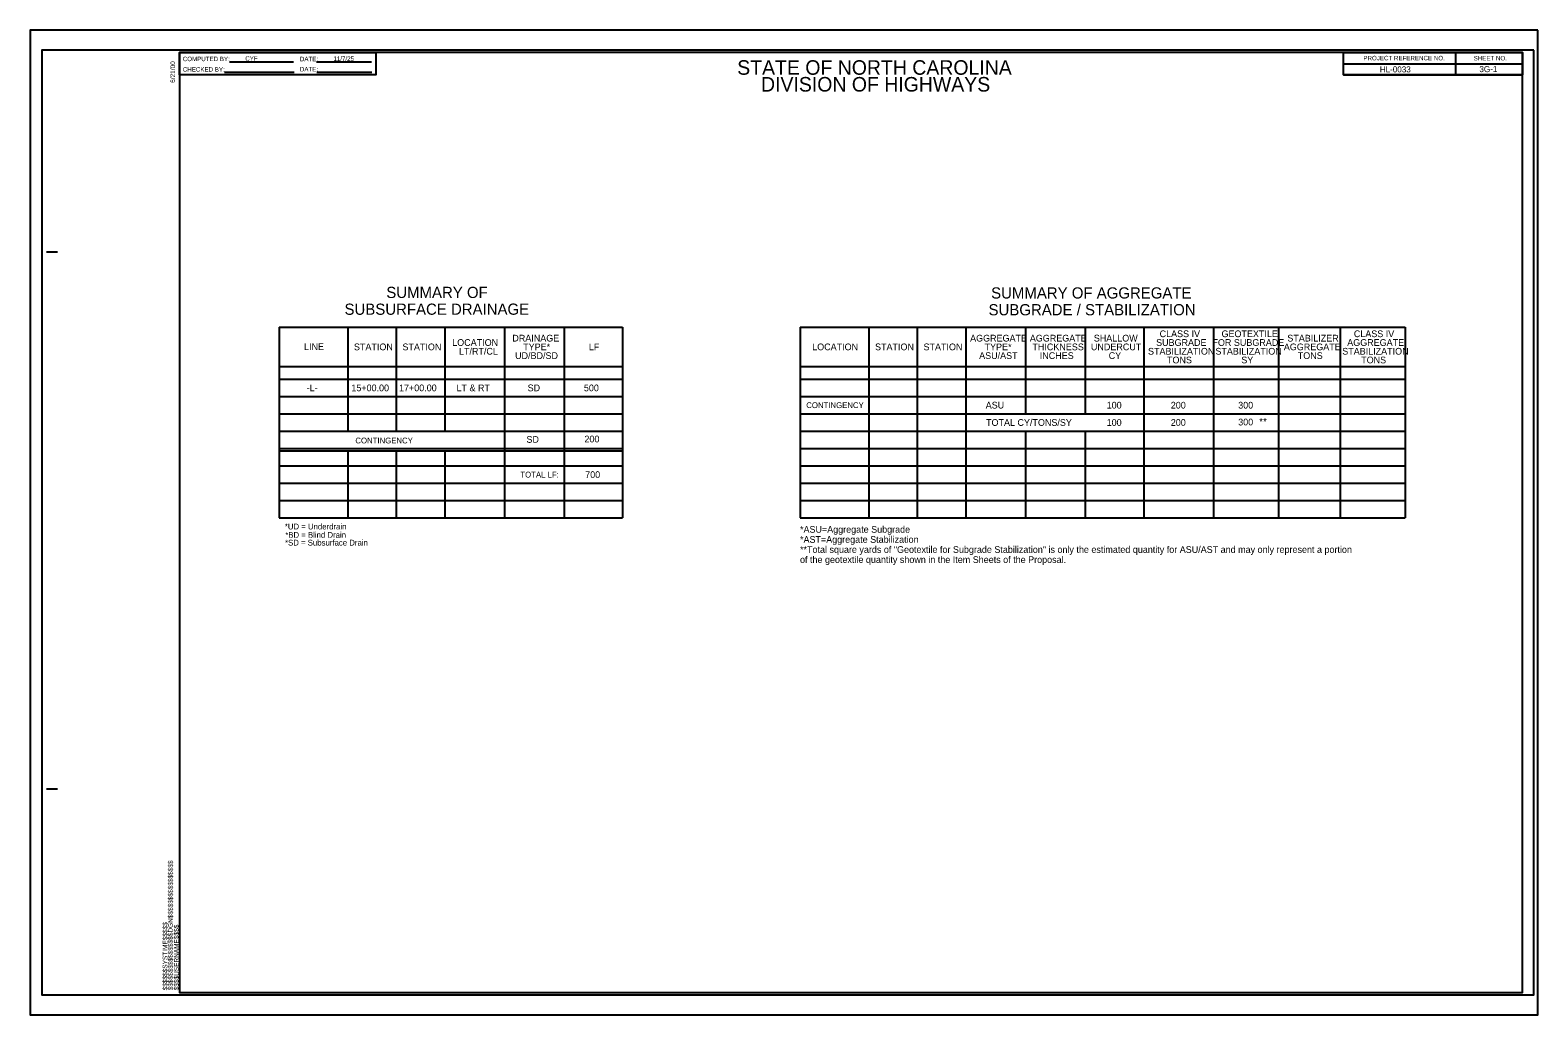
# Model space of a CAD drawing. Extents: x 971219 to 971893, y 692895 to 693335.
import ezdxf

# ---------------------------------------------------------------- set-up
doc = ezdxf.new("R2010")
doc.units = 0
for name, color, linetype in [('Old_Level_1', 7, 'Continuous'), ('Sheet Cutting Line CELL', 7, 'Continuous'), ('Sheet Data Field CELL', 7, 'Continuous'), ('Sheet Plot Border Inside CELL', 7, 'Continuous'), ('Sheet Plot Border Outside CELL', 7, 'Continuous'), ('Sheet Sticker Preliminary CELL', 7, 'Continuous'), ('Sheet Summary Earthwork CELL', 7, 'Continuous')]:
    doc.layers.add(name, color=color, linetype=linetype)

msp = doc.modelspace()

# ---------------------------------------------------------------- linework, layer by layer
at = {"layer": 'Sheet Cutting Line CELL'}
for p, q in [((971893.09, 693334.98), (971219.49, 693334.98)), ((971219.49, 693334.98), (971219.49, 692894.98)), ((971219.49, 692894.98), (971893.09, 692894.98))]:
    msp.add_line(p, q, dxfattribs=at)
at = {"layer": 'Sheet Plot Border Inside CELL'}
msp.add_lwpolyline([(971891.29, 693326), (971224.69, 693326), (971224.69, 692903.96), (971891.29, 692903.96)], close=True, dxfattribs=at)
at = {"layer": 'Sheet Plot Border Outside CELL'}
msp.add_lwpolyline([(971893.09, 693334.98), (971219.49, 693334.98), (971219.49, 692894.98), (971893.09, 692894.98)], close=True, dxfattribs=at)
at = {"layer": 'Sheet Sticker Preliminary CELL'}
for p, q in [((971856.29, 693324.96), (971856.29, 693314.96)), ((971308.55, 693320.82), (971337.17, 693320.82)), ((971347.49, 693320.76), (971372.05, 693320.76)), ((971806.27, 693319.96), (971886.29, 693319.96)), ((971306.37, 693316.14), (971337.45, 693316.14)), ((971347.55, 693316.16), (971372.11, 693316.16)), ((971806.27, 693314.96), (971886.29, 693314.96)), ((971226.73, 693235.98), (971231.73, 693235.98)), ((971459.63, 693202.24), (971459.63, 693202.24)), ((971692.44, 693202.24), (971692.44, 693202.24)), ((971226.73, 692995.98), (971231.73, 692995.98))]:
    msp.add_line(p, q, dxfattribs=at)
for points in [[(971886.29, 693324.98), (971286.29, 693324.98), (971286.29, 692904.98), (971886.29, 692904.98)], [(971286.29, 693324.98), (971373.89, 693324.98), (971373.89, 693314.98), (971286.29, 693314.98)], [(971806.27, 693324.98), (971886.29, 693324.98), (971886.29, 693314.96), (971806.27, 693314.96)]]:
    msp.add_lwpolyline(points, close=True, dxfattribs=at)
at = {"layer": 'Sheet Summary Earthwork CELL'}
for p, q in [((971330.79, 693202.2), (971330.79, 693117.13)), ((971330.79, 693202.2), (971484.19, 693202.2)), ((971361.39, 693202.2), (971361.39, 693155.8)), ((971383.04, 693202.2), (971383.04, 693155.8)), ((971404.7, 693202.2), (971404.7, 693155.8)), ((971431.43, 693202.2), (971431.43, 693163.53)), ((971458.03, 693202.2), (971458.03, 693163.53)), ((971484.19, 693202.2), (971484.19, 693117.13)), ((971563.59, 693202.2), (971563.59, 693117.13)), ((971563.59, 693202.2), (971833.86, 693202.2)), ((971594.19, 693202.2), (971594.19, 693117.13)), ((971615.85, 693202.2), (971615.85, 693117.13)), ((971637.51, 693202.2), (971637.51, 693117.13)), ((971664.23, 693202.2), (971664.23, 693163.53)), ((971690.84, 693202.2), (971690.84, 693163.53)), ((971716.99, 693202.2), (971716.99, 693117.13)), ((971748.17, 693202.2), (971748.17, 693117.13)), ((971748.17, 693202.2), (971748.17, 693117.13)), ((971777.19, 693202.2), (971777.19, 693117.13)), ((971777.19, 693202.2), (971777.19, 693117.13)), ((971804.84, 693202.2), (971804.84, 693117.13)), ((971804.84, 693202.2), (971804.84, 693117.13)), ((971833.86, 693202.2), (971833.86, 693117.13)), ((971833.86, 693202.2), (971833.86, 693117.13)), ((971330.79, 693184.7), (971484.19, 693184.7)), ((971563.59, 693184.7), (971833.86, 693184.7)), ((971330.79, 693179), (971484.19, 693179)), ((971563.59, 693179), (971833.86, 693179)), ((971330.79, 693171.27), (971484.19, 693171.27)), ((971563.59, 693171.27), (971833.86, 693171.27)), ((971330.79, 693163.53), (971484.19, 693163.53)), ((971431.43, 693163.53), (971431.43, 693117.13)), ((971458.03, 693163.53), (971458.03, 693117.13)), ((971563.59, 693163.53), (971833.86, 693163.53)), ((971330.79, 693155.8), (971484.19, 693155.8)), ((971563.59, 693155.8), (971833.86, 693155.8)), ((971664.23, 693155.8), (971664.23, 693117.13)), ((971690.84, 693155.8), (971690.84, 693117.13)), ((971330.79, 693148.06), (971484.19, 693148.06)), ((971563.59, 693148.06), (971833.86, 693148.06)), ((971330.76, 693147), (971484.15, 693147)), ((971361.39, 693147), (971361.39, 693117.13)), ((971383.04, 693147), (971383.04, 693117.13)), ((971404.7, 693147), (971404.7, 693117.13)), ((971330.79, 693140.33), (971484.19, 693140.33)), ((971563.59, 693140.33), (971833.86, 693140.33)), ((971330.79, 693132.6), (971484.19, 693132.6)), ((971563.59, 693132.6), (971833.86, 693132.6)), ((971330.79, 693124.86), (971484.19, 693124.86)), ((971563.59, 693124.86), (971833.86, 693124.86)), ((971330.79, 693117.13), (971484.19, 693117.13)), ((971563.59, 693117.13), (971833.86, 693117.13))]:
    msp.add_line(p, q, dxfattribs=at)

# ---------------------------------------------------------------- texts
at = {"layer": 'Old_Level_1'}
for s, height, p in [('-L-', 3, (971343.01, 693173.63)), ('15+00.00', 3, (971362.99, 693173.63)), ('17+00.00', 3, (971384.28, 693173.63)), ('LT & RT', 3, (971409.97, 693173.63)), ('SD', 3, (971441.75, 693173.63)), ('500', 3, (971466.88, 693173.63)), ('CONTINGENCY', 2.6, (971566.24, 693166.1)), ('ASU', 3, (971646.41, 693165.91)), ('100', 3, (971700.45, 693165.9)), ('200', 3, (971729.11, 693165.9)), ('300', 3, (971759.21, 693165.9)), ('300', 3, (971759.22, 693158.35)), ('TOTAL CY/TONS/SY', 3, (971646.56, 693158.17)), ('100', 3, (971700.45, 693158.17)), ('200', 3, (971729.11, 693158.17)), ('CONTINGENCY', 2.6, (971364.79, 693150.31)), ('SD', 3, (971441.23, 693150.6)), ('200', 3, (971467.12, 693150.79)), ('TOTAL LF:', 2.6, (971438.51, 693135.07)), ('700', 3, (971467.47, 693134.9)), ('*UD = Underdrain', 2.6, (971333.27, 693111.88)), ('*BD = Blind Drain', 2.6, (971333.47, 693108.13)), ('*ASU=Aggregate Subgrade', 3, (971563.45, 693110.4)), ('*AST=Aggregate Stabilization', 3, (971563.45, 693105.9)), ('*SD = Subsurface Drain', 2.6, (971333.37, 693104.67)), ('**Total square yards of "Geotextile for Subgrade Stabilization" is only the estimated quantity for ASU/AST and may only represent a portion', 3, (971563.45, 693101.4)), ('of the geotextile quantity shown in the Item Sheets of the Proposal.', 3, (971563.45, 693096.9))]:
    msp.add_text(s, height=height, dxfattribs=at).set_placement(p)
at = {"layer": 'Sheet Data Field CELL'}
for s, height, p in [('CYF', 2, (971315.61, 693321.32)), ('11/7/25', 2, (971354.99, 693321.26)), ('HL-0033', 2.7, (971822.47, 693316.1)), ('3G-1', 2.7, (971866.98, 693316.22))]:
    msp.add_text(s, height=height, dxfattribs=at).set_placement(p)
at = {"layer": 'Sheet Sticker Preliminary CELL'}
for s, height, p in [('COMPUTED BY:', 1.9999, (971287.67, 693321.12)), ('DATE:', 2, (971340.01, 693321.08)), ('PROJECT REFERENCE NO.', 2, (971815.15, 693321.5)), ('SHEET NO.', 2, (971864.41, 693321.46)), ('CHECKED BY:', 1.9999, (971287.71, 693316.44)), ('DATE:', 2, (971340.01, 693316.52)), ('STATE OF NORTH CAROLINA', 6.5, (971535.39, 693315.04)), ('DIVISION OF HIGHWAYS', 6.5, (971546.03, 693307.54)), ('LINE', 3, (971341.85, 693192.08)), ('LOCATION', 3, (971408.06, 693193.9)), ('DRAINAGE ', 3, (971434.92, 693195.85)), ('AGGREGATE', 3, (971639.45, 693195.85)), ('AGGREGATE', 3, (971666.12, 693195.85)), ('SHALLOW', 3, (971694.7, 693195.85)), ('SUBGRADE', 3, (971722.54, 693193.9)), ('CLASS IV', 3, (971724.11, 693197.8)), ('FOR SUBGRADE', 3, (971747.71, 693193.9)), ('GEOTEXTILE', 3, (971751.77, 693197.8)), ('STABILIZER', 3, (971781.17, 693195.85)), ('AGGREGATE', 3, (971807.93, 693193.9)), ('CLASS IV', 3, (971810.88, 693197.8)), ('STATION', 3, (971364.16, 693191.95)), ('STATION', 3, (971385.82, 693191.95)), ('LT/RT/CL', 3, (971411.08, 693190)), ('UD/BD/SD', 3, (971436.15, 693188.05)), ('TYPE*', 3, (971439.77, 693191.95)), ('LF', 3, (971469.09, 693191.95)), ('LOCATION', 3, (971568.89, 693191.95)), ('STATION', 3, (971596.97, 693191.95)), ('STATION', 3, (971618.63, 693191.95)), ('ASU/AST', 3, (971643.49, 693188.05)), ('TYPE*', 3, (971645.91, 693191.95)), ('THICKNESS', 3, (971667.27, 693191.95)), ('INCHES', 3, (971670.57, 693188.05)), ('UNDERCUT', 3, (971693.42, 693191.95)), ('CY', 3, (971701.36, 693188.05)), ('STABILIZATION', 3, (971718.93, 693190)), ('TONS', 3, (971727.4, 693186.1)), ('STABILIZATION', 3, (971749.03, 693190)), ('SY', 3, (971760.6, 693186.1)), ('AGGREGATE', 3, (971779.6, 693191.95)), ('TONS', 3, (971785.83, 693188.05)), ('STABILIZATION', 3, (971805.7, 693190)), ('TONS', 3, (971814.17, 693186.1)), ('**', 3.267, (971768.61, 693158.43))]:
    msp.add_text(s, height=height, dxfattribs=at).set_placement(p)
for s, height, rotation, p in [('6/21/00', 2.1, 90, (971284.23, 693311.43)), ('SUMMARY OF', 5, 0.01193, (971378.61, 693215.29)), ('SUMMARY OF AGGREGATE ', 5, 0.01193, (971648.83, 693215.05)), ('SUBSURFACE DRAINAGE', 5, 0.01193, (971359.95, 693207.79)), ('SUBGRADE / STABILIZATION', 5, 0.01193, (971647.68, 693207.55)), ('$$$$$$$$$$$$$$$$DGN$$$$$$$$$$$$$$$$', 2.1, 90, (971283.23, 692905.92)), ('$$$$$$SYSTIME$$$$$', 2.1, 90, (971280.81, 692905.92)), ('$$$$USERNAME$$$$', 2.1, 90, (971285.86, 692905.93))]:
    msp.add_text(s, height=height, rotation=rotation, dxfattribs=at).set_placement(p)

doc.saveas('drawing.dxf')
